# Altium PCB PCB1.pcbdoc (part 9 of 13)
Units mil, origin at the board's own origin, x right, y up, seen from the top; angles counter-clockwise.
Board outline 5895.51 x 5895.51 mil, 8 copper layers (Top Layer, L2_GND1, L3_SIG1, L4_GND2, L5_PWR, L6_SIG2, L7_GND3, Bottom Layer), stack 63.761 mil thick; 673 components, 558 nets, 2797 pads, 1861 vias.
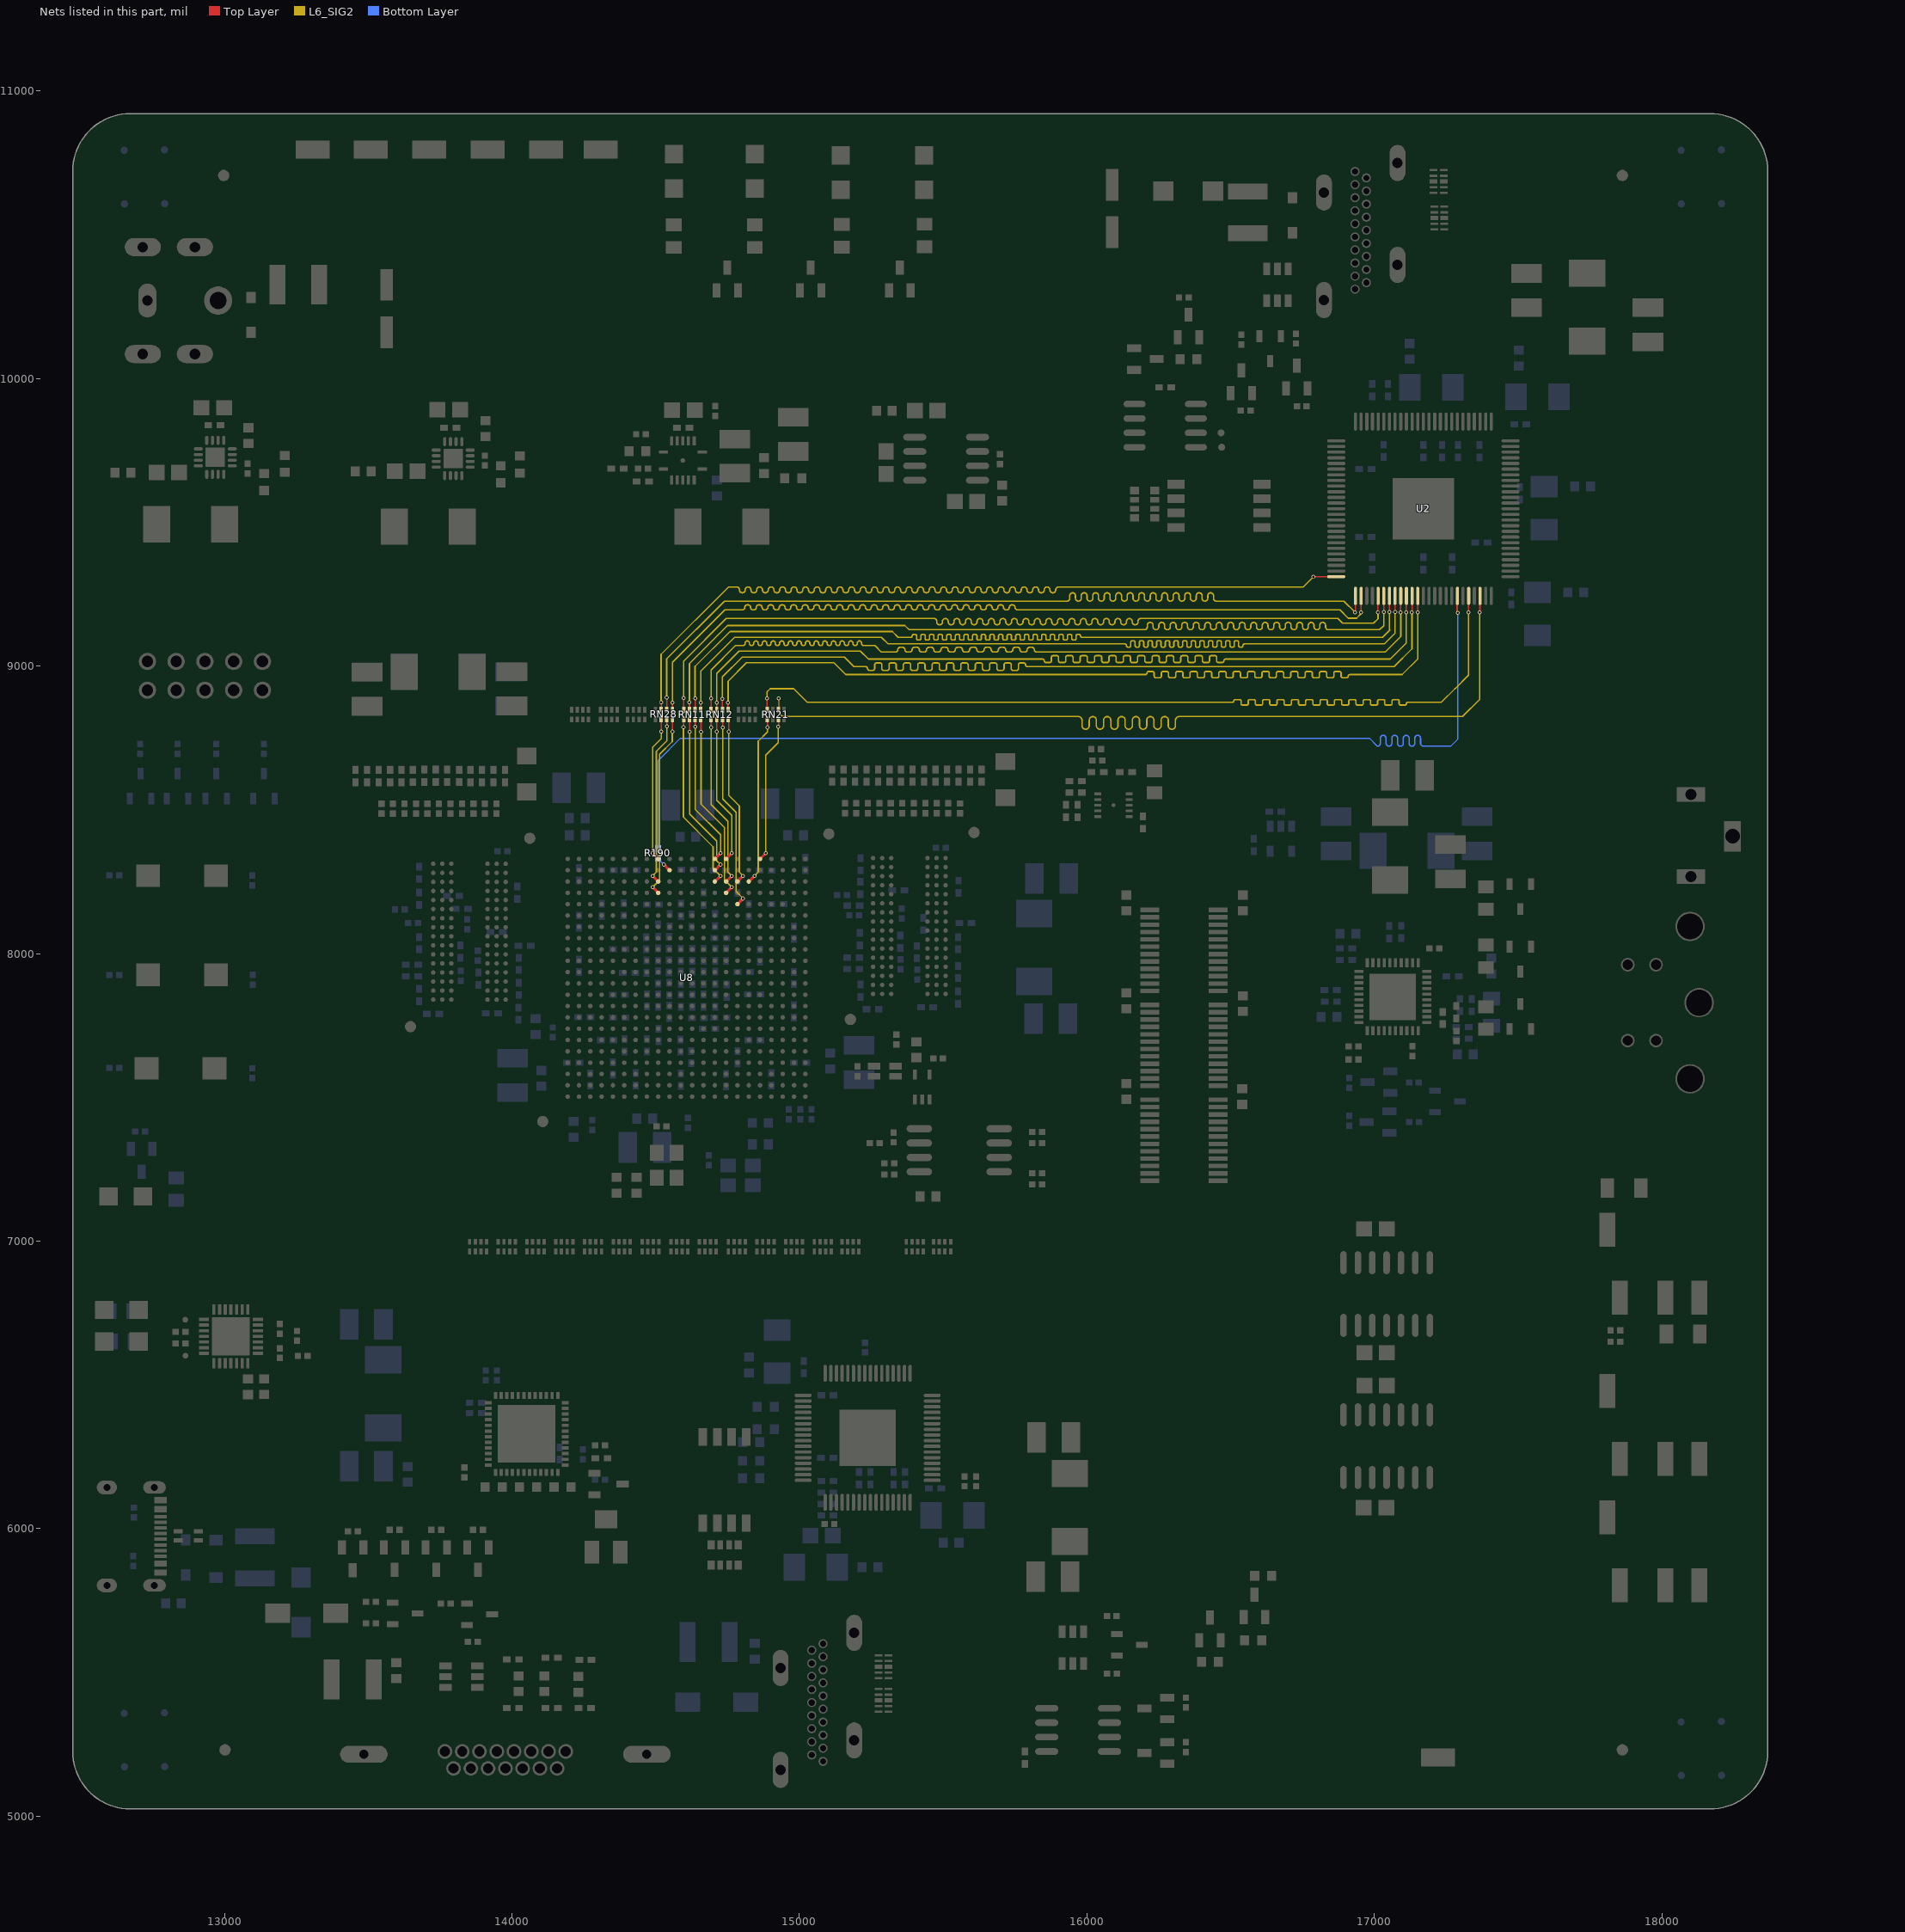
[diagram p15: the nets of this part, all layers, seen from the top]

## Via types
v1: diameter 23.62, hole 15.75, Top Layer to Bottom Layer, 621 vias
v2: diameter 13.8, hole 7.9, Top Layer to Bottom Layer, 567 vias
v3: diameter 13.78, hole 7.87, Top Layer to Bottom Layer, 529 vias
v4: diameter 13.78, hole 7.9, Top Layer to Bottom Layer, 114 vias
v5: diameter 15.75, hole 7.87, Top Layer to Bottom Layer, 16 vias
v6: diameter 24, hole 12, Top Layer to Bottom Layer, 10 vias
v7: diameter 11.81, hole 7.87, Top Layer to Bottom Layer, 4 vias

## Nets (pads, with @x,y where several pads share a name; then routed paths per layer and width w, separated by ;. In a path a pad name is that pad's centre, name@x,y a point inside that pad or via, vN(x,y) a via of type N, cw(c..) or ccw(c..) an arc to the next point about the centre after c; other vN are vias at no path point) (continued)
TFP401_D13: RN28.6 U2.25 | length 3320.2
  Top Layer w4.7: RN28.6@14519.06,8848.52 v3(14519.06,8874) ; v4(16787.36,9310) 16867.87,9310 U2.25@16868.3,9310.42
  L6_SIG2 w5: v3(14519.06,8874) 14519.06,9040.71 14753.36,9275 14781.48,9275 cw(c14781.48,9265) 14791.48,9265 14791.48,9264.5 ccw(c14801.48,9264.5) 14811.48,9264.5 14811.48,9265 cw(c14821.48,9265) 14831.48,9265 14831.48,9264.5 ccw(c14841.48,9264.5) 14851.48,9264.5 14851.48,9265 cw(c14861.48,9265) 14871.48,9265 14871.48,9264.5 ccw(c14881.48,9264.5) 14891.48,9264.5 14891.48,9265 cw(c14901.48,9265) 14911.48,9265 14911.48,9264.5 ccw(c14921.48,9264.5) 14931.48,9264.5 14931.48,9265 cw(c14941.48,9265) 14951.48,9265 14951.48,9264.5 ccw(c14961.48,9264.5) 14971.48,9264.5 14971.48,9265 cw(c14981.48,9265) 14991.48,9265 14991.48,9264.5 ccw(c15001.48,9264.5) 15011.48,9264.5 15011.48,9265 cw(c15021.48,9265) 15031.48,9265 15031.48,9264.5 ccw(c15041.48,9264.5) 15051.48,9264.5 15051.48,9265 cw(c15061.48,9265) 15071.48,9265 15071.48,9264.5 ccw(c15081.48,9264.5) 15091.48,9264.5 15091.48,9265 cw(c15101.48,9265) 15111.48,9265 15111.48,9264.5 ccw(c15121.48,9264.5) 15131.48,9264.5 15131.48,9265 cw(c15141.48,9265) 15151.48,9265 15151.48,9264.5 ccw(c15161.48,9264.5) 15171.48,9264.5 15171.48,9265 cw(c15181.48,9265) 15191.48,9265 15191.48,9264.5 ccw(c15201.48,9264.5) 15211.48,9264.5 15211.48,9265 cw(c15221.48,9265) 15231.48,9265 15231.48,9264.5 ccw(c15241.48,9264.5) 15251.48,9264.5 15251.48,9265 cw(c15261.48,9265) 15271.48,9265 15271.48,9264.5 ccw(c15281.48,9264.5) 15291.48,9264.5 15291.48,9265 cw(c15301.48,9265) 15311.48,9265 15311.48,9264.5 ccw(c15321.48,9264.5) 15331.48,9264.5 15331.48,9265 cw(c15341.48,9265) 15351.48,9265 15351.48,9264.5 ccw(c15361.48,9264.5) 15371.48,9264.5 15371.48,9265 cw(c15381.48,9265) 15391.48,9265 15391.48,9264.5 ccw(c15401.48,9264.5) 15411.48,9264.5 15411.48,9265 cw(c15421.48,9265) 15431.48,9265 15431.48,9264.5 ccw(c15441.48,9264.5) 15451.48,9264.5 15451.48,9265 cw(c15461.48,9265) 15471.48,9265 15471.48,9264.5 ccw(c15481.48,9264.5) 15491.48,9264.5 15491.48,9265 cw(c15501.48,9265) 15511.48,9265 15511.48,9264.5 ccw(c15521.48,9264.5) 15531.48,9264.5 15531.48,9265 cw(c15541.48,9265) 15551.48,9265 15551.48,9264.5 ccw(c15561.48,9264.5) 15571.48,9264.5 15571.48,9265 cw(c15581.48,9265) 15591.48,9265 15591.48,9264.5 ccw(c15601.48,9264.5) 15611.48,9264.5 15611.48,9265 cw(c15621.48,9265) 15631.48,9265 15631.48,9264.5 ccw(c15641.48,9264.5) 15651.48,9264.5 15651.48,9265 cw(c15661.48,9265) 15671.48,9265 15671.48,9264.5 ccw(c15681.48,9264.5) 15691.48,9264.5 15691.48,9265 cw(c15701.48,9265) 15711.48,9265 15711.48,9264.5 ccw(c15721.48,9264.5) 15731.48,9264.5 15731.48,9265 cw(c15741.48,9265) 15751.48,9265 15751.48,9264.5 ccw(c15761.48,9264.5) 15771.48,9264.5 15771.48,9265 cw(c15781.48,9265) 15791.48,9265 15791.48,9264.5 ccw(c15801.48,9264.5) 15811.48,9264.5 15811.48,9265 cw(c15821.48,9265) 15831.48,9265 15831.48,9264.5 ccw(c15841.48,9264.5) 15851.48,9264.5 15851.48,9265 cw(c15861.48,9265) 15871.48,9265 15871.48,9264.5 ccw(c15881.48,9264.5) 15891.48,9264.5 15891.48,9265 cw(c15901.48,9265) 15901.48,9275 16752.36,9275 v4(16787.36,9310)
TFP401_D13_FPGA: RN28.3 U8.A9 | length 506.1
  Top Layer w4.7: RN28.3@14519.06,8814.86 14519.25,8814.67 v3(14519.25,8772.11)
  Top Layer w10: v2(14489.26,8349.07) U8.A9@14508.93,8329.4
  L6_SIG2 w5: v2(14489.26,8349.07) 14489.26,8717.62 14519.25,8747.61 v3(14519.25,8772.11)
TFP401_D14: RN28.7 U2.26 | length 3254.3
  Top Layer w4.7: v3(14538.36,8890) 14538.74,8889.61 RN28.7@14538.74,8848.52 ; v4(16932.36,9187) 16934.51,9189.16 U2.26@16934.51,9239.96
  L6_SIG2 w5: v3(14538.36,8890) 14538.36,9025 14738.97,9225.62 15930.31,9225.62 ccw(c15930.31,9235.62) 15940.31,9235.62 15940.31,9244.61 cw(c15950.31,9244.61) 15960.31,9244.61 15960.31,9235.62 ccw(c15970.31,9235.62) 15980.31,9235.62 15980.31,9244.61 cw(c15990.31,9244.61) 16000.31,9244.61 16000.31,9235.62 ccw(c16010.31,9235.62) 16020.31,9235.62 16020.31,9244.61 cw(c16030.31,9244.61) 16040.31,9244.61 16040.31,9235.62 ccw(c16050.31,9235.62) 16060.31,9235.62 16060.31,9244.61 cw(c16070.31,9244.61) 16080.31,9244.61 16080.31,9235.62 ccw(c16090.31,9235.62) 16100.31,9235.62 16100.31,9244.61 cw(c16110.31,9244.61) 16120.31,9244.61 16120.31,9235.62 ccw(c16130.31,9235.62) 16140.31,9235.62 16140.31,9244.61 cw(c16150.31,9244.61) 16160.31,9244.61 16160.31,9235.62 ccw(c16170.31,9235.62) 16180.31,9235.62 16180.31,9244.61 cw(c16190.31,9244.61) 16200.31,9244.61 16200.31,9235.62 ccw(c16210.31,9235.62) 16220.31,9235.62 16220.31,9244.61 cw(c16230.31,9244.61) 16240.31,9244.61 16240.31,9235.62 ccw(c16250.31,9235.62) 16260.31,9235.62 16260.31,9244.61 cw(c16270.31,9244.61) 16280.31,9244.61 16280.31,9235.62 ccw(c16290.31,9235.62) 16300.31,9235.62 16300.31,9244.61 cw(c16310.31,9244.61) 16320.31,9244.61 16320.31,9235.62 ccw(c16330.31,9235.62) 16340.31,9235.62 16340.31,9244.61 cw(c16350.31,9244.61) 16360.31,9244.61 16360.31,9235.62 ccw(c16370.31,9235.62) 16380.31,9235.62 16380.31,9244.61 cw(c16390.31,9244.61) 16400.31,9244.61 16400.31,9235.62 ccw(c16410.31,9235.62) 16420.31,9235.62 16420.31,9244.61 cw(c16430.31,9244.61) 16440.31,9244.61 16440.31,9235.62 ccw(c16450.31,9235.62) 16450.31,9225.62 16893.74,9225.62 v4(16932.36,9187)
TFP401_D14_FPGA: RN28.2 U8.C9 | length 593
  Top Layer w4.7: v3(14538.72,8790.02) RN28.2@14538.74,8814.86
  Top Layer w10: v2(14489.26,8270.32) U8.C9@14508.93,8250.65
  L6_SIG2 w5: v2(14489.26,8270.32) 14502.23,8283.29 14502.23,8703.72 14538.89,8740.39 14538.89,8789.85 v3(14538.72,8790.02)
TFP401_D15: RN28.8 U2.27 | length 3184.4
  Top Layer w4.7: RN28.8@14558.43,8848.52 v3(14558.43,8873) ; U2.27@16952.55,9241.33 16953.36,9240.52 v4(16953.36,9186)
  L6_SIG2 w5: v3(14558.43,8873) 14558.43,9013.08 14740.74,9195.38 14801.47,9195.38 ccw(c14801.47,9203.97) 14810.06,9203.97 cw(c14818.64,9203.97) 14818.64,9212.56 14821.47,9212.56 cw(c14821.47,9203.97) 14830.06,9203.97 ccw(c14838.64,9203.97) 14838.64,9195.38 14841.47,9195.38 ccw(c14841.47,9203.97) 14850.06,9203.97 cw(c14858.64,9203.97) 14858.64,9212.56 14861.47,9212.56 cw(c14861.47,9203.97) 14870.06,9203.97 ccw(c14878.64,9203.97) 14878.64,9195.38 14881.47,9195.38 ccw(c14881.47,9203.97) 14890.06,9203.97 cw(c14898.64,9203.97) 14898.64,9212.56 14901.47,9212.56 cw(c14901.47,9203.97) 14910.06,9203.97 ccw(c14918.64,9203.97) 14918.64,9195.38 14921.47,9195.38 ccw(c14921.47,9203.97) 14930.06,9203.97 cw(c14938.64,9203.97) 14938.64,9212.56 14941.47,9212.56 cw(c14941.47,9203.97) 14950.06,9203.97 ccw(c14958.64,9203.97) 14958.64,9195.38 14961.47,9195.38 ccw(c14961.47,9203.97) 14970.06,9203.97 cw(c14978.64,9203.97) 14978.64,9212.56 14981.47,9212.56 cw(c14981.47,9203.97) 14990.06,9203.97 ccw(c14998.64,9203.97) 14998.64,9195.38 15001.47,9195.38 ccw(c15001.47,9203.97) 15010.06,9203.97 cw(c15018.64,9203.97) 15018.64,9212.56 15021.47,9212.56 cw(c15021.47,9203.97) 15030.06,9203.97 ccw(c15038.64,9203.97) 15038.64,9195.38 15041.47,9195.38 ccw(c15041.47,9203.97) 15050.06,9203.97 cw(c15058.64,9203.97) 15058.64,9212.56 15061.47,9212.56 cw(c15061.47,9203.97) 15070.06,9203.97 ccw(c15078.64,9203.97) 15078.64,9195.38 15081.47,9195.38 ccw(c15081.47,9203.97) 15090.06,9203.97 cw(c15098.64,9203.97) 15098.64,9212.56 15101.47,9212.56 cw(c15101.47,9203.97) 15110.06,9203.97 ccw(c15118.64,9203.97) 15118.64,9195.38 15121.47,9195.38 ccw(c15121.47,9203.97) 15130.06,9203.97 cw(c15138.64,9203.97) 15138.64,9212.56 15141.47,9212.56 cw(c15141.47,9203.97) 15150.06,9203.97 ccw(c15158.64,9203.97) 15158.64,9195.38 15161.47,9195.38 ccw(c15161.47,9203.97) 15170.06,9203.97 cw(c15178.64,9203.97) 15178.64,9212.56 15181.47,9212.56 cw(c15181.47,9203.97) 15190.06,9203.97 ccw(c15198.64,9203.97) 15198.64,9195.38 15201.47,9195.38 ccw(c15201.47,9203.97) 15210.06,9203.97 cw(c15218.64,9203.97) 15218.64,9212.56 15221.47,9212.56 cw(c15221.47,9203.97) 15230.06,9203.97 ccw(c15238.64,9203.97) 15238.64,9195.38 15241.47,9195.38 ccw(c15241.47,9203.97) 15250.06,9203.97 cw(c15258.64,9203.97) 15258.64,9212.56 15261.47,9212.56 cw(c15261.47,9203.97) 15270.06,9203.97 ccw(c15278.64,9203.97) 15278.64,9195.38 15281.47,9195.38 ccw(c15281.47,9203.97) 15290.06,9203.97 cw(c15298.64,9203.97) 15298.64,9212.56 15301.47,9212.56 cw(c15301.47,9203.97) 15310.06,9203.97 ccw(c15318.64,9203.97) 15318.64,9195.38 15321.47,9195.38 ccw(c15321.47,9203.97) 15330.06,9203.97 cw(c15338.64,9203.97) 15338.64,9212.56 15341.47,9212.56 cw(c15341.47,9203.97) 15350.06,9203.97 ccw(c15358.64,9203.97) 15358.64,9195.38 15361.47,9195.38 ccw(c15361.47,9203.97) 15370.06,9203.97 cw(c15378.64,9203.97) 15378.64,9212.56 15381.47,9212.56 cw(c15381.47,9203.97) 15390.06,9203.97 ccw(c15398.64,9203.97) 15398.64,9195.38 15401.47,9195.38 ccw(c15401.47,9203.97) 15410.06,9203.97 cw(c15418.64,9203.97) 15418.64,9212.56 15421.47,9212.56 cw(c15421.47,9203.97) 15430.06,9203.97 ccw(c15438.64,9203.97) 15438.64,9195.38 15441.47,9195.38 ccw(c15441.47,9203.97) 15450.06,9203.97 cw(c15458.64,9203.97) 15458.64,9212.56 15461.47,9212.56 cw(c15461.47,9203.97) 15470.06,9203.97 ccw(c15478.64,9203.97) 15478.64,9195.38 15481.47,9195.38 ccw(c15481.47,9203.97) 15490.06,9203.97 cw(c15498.64,9203.97) 15498.64,9212.56 15501.47,9212.56 cw(c15501.47,9203.97) 15510.06,9203.97 ccw(c15518.64,9203.97) 15518.64,9195.38 15521.47,9195.38 ccw(c15521.47,9203.97) 15530.06,9203.97 cw(c15538.64,9203.97) 15538.64,9212.56 15541.47,9212.56 cw(c15541.47,9203.97) 15550.06,9203.97 ccw(c15558.64,9203.97) 15558.64,9195.38 15561.47,9195.38 ccw(c15561.47,9203.97) 15570.06,9203.97 cw(c15578.64,9203.97) 15578.64,9212.56 15581.47,9212.56 cw(c15581.47,9203.97) 15590.06,9203.97 ccw(c15598.64,9203.97) 15598.64,9195.38 15601.47,9195.38 ccw(c15601.47,9203.97) 15610.06,9203.97 cw(c15618.64,9203.97) 15618.64,9212.56 15621.47,9212.56 cw(c15621.47,9203.97) 15630.06,9203.97 ccw(c15638.64,9203.97) 15638.64,9195.38 15641.47,9195.38 ccw(c15641.47,9203.97) 15650.06,9203.97 cw(c15658.64,9203.97) 15658.64,9212.56 15661.47,9212.56 cw(c15661.47,9203.97) 15670.06,9203.97 ccw(c15678.64,9203.97) 15678.64,9195.38 15681.47,9195.38 ccw(c15681.47,9203.97) 15690.06,9203.97 cw(c15698.64,9203.97) 15698.64,9212.56 15701.47,9212.56 cw(c15701.47,9203.97) 15710.06,9203.97 ccw(c15718.64,9203.97) 15718.64,9195.38 15721.47,9195.38 ccw(c15721.47,9203.97) 15730.06,9203.97 cw(c15738.64,9203.97) 15738.64,9212.56 15741.47,9212.56 cw(c15741.47,9203.97) 15750.06,9203.97 ccw(c15758.64,9203.97) 15758.64,9195.38 16880.05,9195.38 16909.04,9166.39 ; 16909.17,9166.26 16909.04,9166.39 ; 16938.3,9166.39 16937.69,9166.39 ; v4(16953.36,9186) 16953.36,9182.06 16937.69,9166.39 ; 16909.04,9166.39 16937.69,9166.39
TFP401_D15_FPGA: RN28.1 U8.D9 | length 640.4
  Top Layer w4.7: v3(14558.02,8771.64) 14558.43,8772.05 RN28.1@14558.43,8814.86
  Top Layer w10: v2(14489.26,8230.95) U8.D9@14508.93,8211.27
  L6_SIG2 w5: v2(14489.26,8230.95) 14513.82,8255.52 14513.82,8692.94 14557.9,8737.02 14557.9,8771.52 v3(14558.02,8771.64)
TFP401_D16: RN11.5 U2.30 | length 3210.6
  Top Layer w4.7: v3(14597.36,8889) 14597.83,8888.53 RN11.5@14597.83,8847.83 ; v4(17012.36,9187) U2.30@17012.36,9237.18
  L6_SIG2 w5: v3(14597.36,8889) 14597.36,9017 14745.58,9165.22 15467.67,9165.22 cw(c15467.67,9155.22) 15477.67,9155.22 15477.67,9153.33 ccw(c15487.67,9153.33) 15497.67,9153.33 15497.67,9155.22 cw(c15507.67,9155.22) 15517.67,9155.22 15517.67,9153.33 ccw(c15527.67,9153.33) 15537.67,9153.33 15537.67,9155.22 cw(c15547.67,9155.22) 15557.67,9155.22 15557.67,9153.33 ccw(c15567.67,9153.33) 15577.67,9153.33 15577.67,9155.22 cw(c15587.67,9155.22) 15597.67,9155.22 15597.67,9153.33 ccw(c15607.67,9153.33) 15617.67,9153.33 15617.67,9155.22 cw(c15627.67,9155.22) 15637.67,9155.22 15637.67,9153.33 ccw(c15647.67,9153.33) 15657.67,9153.33 15657.67,9155.22 cw(c15667.67,9155.22) 15677.67,9155.22 15677.67,9153.33 ccw(c15687.67,9153.33) 15697.67,9153.33 15697.67,9155.22 cw(c15707.67,9155.22) 15717.67,9155.22 15717.67,9153.33 ccw(c15727.67,9153.33) 15737.67,9153.33 15737.67,9155.22 cw(c15747.67,9155.22) 15757.67,9155.22 15757.67,9153.33 ccw(c15767.67,9153.33) 15777.67,9153.33 15777.67,9155.22 cw(c15787.67,9155.22) 15797.67,9155.22 15797.67,9153.33 ccw(c15807.67,9153.33) 15817.67,9153.33 15817.67,9155.22 cw(c15827.67,9155.22) 15837.67,9155.22 15837.67,9153.33 ccw(c15847.67,9153.33) 15857.67,9153.33 15857.67,9155.22 cw(c15867.67,9155.22) 15877.67,9155.22 15877.67,9153.33 ccw(c15887.67,9153.33) 15897.67,9153.33 15897.67,9155.22 cw(c15907.67,9155.22) 15917.67,9155.22 15917.67,9153.33 ccw(c15927.67,9153.33) 15937.67,9153.33 15937.67,9155.22 cw(c15947.67,9155.22) 15957.67,9155.22 15957.67,9153.33 ccw(c15967.67,9153.33) 15977.67,9153.33 15977.67,9155.22 cw(c15987.67,9155.22) 15997.67,9155.22 15997.67,9153.33 ccw(c16007.67,9153.33) 16017.67,9153.33 16017.67,9155.22 cw(c16027.67,9155.22) 16037.67,9155.22 16037.67,9153.33 ccw(c16047.67,9153.33) 16057.67,9153.33 16057.67,9155.22 cw(c16067.67,9155.22) 16077.67,9155.22 16077.67,9153.33 ccw(c16087.67,9153.33) 16097.67,9153.33 16097.67,9155.22 cw(c16107.67,9155.22) 16117.67,9155.22 16117.67,9153.33 ccw(c16127.67,9153.33) 16137.67,9153.33 16137.67,9155.22 cw(c16147.67,9155.22) 16157.67,9155.22 16157.67,9153.33 ccw(c16167.67,9153.33) 16177.67,9153.33 16177.67,9155.22 cw(c16187.67,9155.22) 16187.67,9165.22 16873.04,9165.22 16889.04,9149.21 16996.78,9149.21 16996.86,9149.13 16997.09,9149.13 17012.36,9164.39 v4(17012.36,9187)
TFP401_D16_FPGA: RN11.4 U8.C14 | length 625.5
  Top Layer w4.7: v3(14596.62,8787.81) 14597.83,8789.02 RN11.4@14597.83,8814.17
  Top Layer w10: U8.C14@14705.78,8250.65 v2(14725.46,8270.32)
  L6_SIG2 w5: v3(14596.62,8787.81) 14596.62,8474.41 14699.84,8371.19 14699.84,8295.94 v2(14725.46,8270.32)
TFP401_D17: RN11.6 U2.31 | length 3279.6
  Top Layer w4.7: v3(14617.36,8874) 14617.52,8873.84 RN11.6@14617.52,8847.83 ; U2.31@17031.51,9237.54 17032.36,9236.7 v4(17032.36,9188)
  L6_SIG2 w5: v3(14617.36,8874) 14617.36,9009 14749.43,9141.07 15366.72,9141.07 15381.56,9126.23 16199.99,9126.23 ccw(c16199.99,9136.23) 16209.99,9136.23 16209.99,9141.66 cw(c16219.99,9141.66) 16229.99,9141.66 16229.99,9136.23 ccw(c16239.99,9136.23) 16249.99,9136.23 16249.99,9141.66 cw(c16259.99,9141.66) 16269.99,9141.66 16269.99,9136.23 ccw(c16279.99,9136.23) 16289.99,9136.23 16289.99,9141.66 cw(c16299.99,9141.66) 16309.99,9141.66 16309.99,9136.23 ccw(c16319.99,9136.23) 16329.99,9136.23 16329.99,9141.66 cw(c16339.99,9141.66) 16349.99,9141.66 16349.99,9136.23 ccw(c16359.99,9136.23) 16369.99,9136.23 16369.99,9141.66 cw(c16379.99,9141.66) 16389.99,9141.66 16389.99,9136.23 ccw(c16399.99,9136.23) 16409.99,9136.23 16409.99,9141.66 cw(c16419.99,9141.66) 16429.99,9141.66 16429.99,9136.23 ccw(c16439.99,9136.23) 16449.99,9136.23 16449.99,9141.66 cw(c16459.99,9141.66) 16469.99,9141.66 16469.99,9136.23 ccw(c16479.99,9136.23) 16489.99,9136.23 16489.99,9141.66 cw(c16499.99,9141.66) 16509.99,9141.66 16509.99,9136.23 ccw(c16519.99,9136.23) 16529.99,9136.23 16529.99,9141.66 cw(c16539.99,9141.66) 16549.99,9141.66 16549.99,9136.23 ccw(c16559.99,9136.23) 16569.99,9136.23 16569.99,9141.66 cw(c16579.99,9141.66) 16589.99,9141.66 16589.99,9136.23 ccw(c16599.99,9136.23) 16609.99,9136.23 16609.99,9141.66 cw(c16619.99,9141.66) 16629.99,9141.66 16629.99,9136.23 ccw(c16639.99,9136.23) 16649.99,9136.23 16649.99,9141.66 cw(c16659.99,9141.66) 16669.99,9141.66 16669.99,9136.23 ccw(c16679.99,9136.23) 16689.99,9136.23 16689.99,9141.66 cw(c16699.99,9141.66) 16709.99,9141.66 16709.99,9136.23 ccw(c16719.99,9136.23) 16729.99,9136.23 16729.99,9141.66 cw(c16739.99,9141.66) 16749.99,9141.66 16749.99,9136.23 ccw(c16759.99,9136.23) 16769.99,9136.23 16769.99,9141.66 cw(c16779.99,9141.66) 16789.99,9141.66 16789.99,9136.23 ccw(c16799.99,9136.23) 16809.99,9136.23 16809.99,9141.66 cw(c16819.99,9141.66) 16829.99,9141.66 16829.99,9136.23 ccw(c16839.99,9136.23) 16839.99,9126.23 17018.25,9126.23 17032.33,9140.32 v4(17032.36,9188)
TFP401_D17_FPGA: RN11.3 U8.B14 | length 577
  Top Layer w4.7: RN11.3@14617.52,8814.17 14618.37,8813.32 v3(14618.37,8770.75)
  Top Layer w10: U8.B14@14705.78,8290.01 v2(14725.46,8309.69)
  L6_SIG2 w5: v3@14618.31,8770.69 14618.31,8485.16 14712.29,8391.18 14712.29,8322.86 v2(14725.46,8309.69)
TFP401_D18: RN11.7 U2.32 | length 3341.1
  Top Layer w4.7: RN11.7@14637.2,8847.83 v3(14637.2,8888) ; U2.32@17050.76,9236.48 17052.36,9234.88 v4(17052.36,9188)
  L6_SIG2 w5: v3(14637.2,8888) 14637.2,8998.84 14758.55,9120.19 15323.32,9120.19 15343.47,9100.05 15387.61,9100.05 ccw(c15387.61,9104.92) 15392.48,9104.92 cw(c15397.35,9104.92) 15397.35,9109.79 15402.61,9109.79 cw(c15402.61,9104.92) 15407.48,9104.92 15407.48,9095.18 ccw(c15412.35,9095.18) 15412.35,9090.31 15417.61,9090.31 ccw(c15417.61,9095.18) 15422.48,9095.18 15422.48,9104.92 cw(c15427.35,9104.92) 15427.35,9109.79 15432.61,9109.79 cw(c15432.61,9104.92) 15437.48,9104.92 15437.48,9095.18 ccw(c15442.35,9095.18) 15442.35,9090.31 15447.61,9090.31 ccw(c15447.61,9095.18) 15452.48,9095.18 15452.48,9104.92 cw(c15457.35,9104.92) 15457.35,9109.79 15462.61,9109.79 cw(c15462.61,9104.92) 15467.48,9104.92 15467.48,9095.18 ccw(c15472.35,9095.18) 15472.35,9090.31 15477.61,9090.31 ccw(c15477.61,9095.18) 15482.48,9095.18 15482.48,9104.92 cw(c15487.35,9104.92) 15487.35,9109.79 15492.61,9109.79 cw(c15492.61,9104.92) 15497.48,9104.92 15497.48,9095.18 ccw(c15502.35,9095.18) 15502.35,9090.31 15507.61,9090.31 ccw(c15507.61,9095.18) 15512.48,9095.18 15512.48,9104.92 cw(c15517.35,9104.92) 15517.35,9109.79 15522.61,9109.79 cw(c15522.61,9104.92) 15527.48,9104.92 15527.48,9095.18 ccw(c15532.35,9095.18) 15532.35,9090.31 15537.61,9090.31 ccw(c15537.61,9095.18) 15542.48,9095.18 15542.48,9104.92 cw(c15547.35,9104.92) 15547.35,9109.79 15552.61,9109.79 cw(c15552.61,9104.92) 15557.48,9104.92 15557.48,9095.18 ccw(c15562.35,9095.18) 15562.35,9090.31 15567.61,9090.31 ccw(c15567.61,9095.18) 15572.48,9095.18 15572.48,9104.92 cw(c15577.35,9104.92) 15577.35,9109.79 15582.61,9109.79 cw(c15582.61,9104.92) 15587.48,9104.92 15587.48,9095.18 ccw(c15592.35,9095.18) 15592.35,9090.31 15597.61,9090.31 ccw(c15597.61,9095.18) 15602.48,9095.18 15602.48,9104.92 cw(c15607.35,9104.92) 15607.35,9109.79 15612.61,9109.79 cw(c15612.61,9104.92) 15617.48,9104.92 15617.48,9095.18 ccw(c15622.35,9095.18) 15622.35,9090.31 15627.61,9090.31 ccw(c15627.61,9095.18) 15632.48,9095.18 15632.48,9104.92 cw(c15637.35,9104.92) 15637.35,9109.79 15642.61,9109.79 cw(c15642.61,9104.92) 15647.48,9104.92 15647.48,9095.18 ccw(c15652.35,9095.18) 15652.35,9090.31 15657.61,9090.31 ccw(c15657.61,9095.18) 15662.48,9095.18 15662.48,9104.92 cw(c15667.35,9104.92) 15667.35,9109.79 15672.61,9109.79 cw(c15672.61,9104.92) 15677.48,9104.92 15677.48,9095.18 ccw(c15682.35,9095.18) 15682.35,9090.31 15687.61,9090.31 ccw(c15687.61,9095.18) 15692.48,9095.18 15692.48,9104.92 cw(c15697.35,9104.92) 15697.35,9109.79 15702.61,9109.79 cw(c15702.61,9104.92) 15707.48,9104.92 15707.48,9095.18 ccw(c15712.35,9095.18) 15712.35,9090.31 15717.61,9090.31 ccw(c15717.61,9095.18) 15722.48,9095.18 15722.48,9104.92 cw(c15727.35,9104.92) 15727.35,9109.79 15732.61,9109.79 cw(c15732.61,9104.92) 15737.48,9104.92 15737.48,9095.18 ccw(c15742.35,9095.18) 15742.35,9090.31 15747.61,9090.31 ccw(c15747.61,9095.18) 15752.48,9095.18 15752.48,9104.92 cw(c15757.35,9104.92) 15757.35,9109.79 15762.61,9109.79 cw(c15762.61,9104.92) 15767.48,9104.92 15767.48,9095.18 ccw(c15772.35,9095.18) 15772.35,9090.31 15777.61,9090.31 ccw(c15777.61,9095.18) 15782.48,9095.18 15782.48,9104.92 cw(c15787.35,9104.92) 15787.35,9109.79 15792.61,9109.79 cw(c15792.61,9104.92) 15797.48,9104.92 15797.48,9095.18 ccw(c15802.35,9095.18) 15802.35,9090.31 15807.61,9090.31 ccw(c15807.61,9095.18) 15812.48,9095.18 15812.48,9104.92 cw(c15817.35,9104.92) 15817.35,9109.79 15822.61,9109.79 cw(c15822.61,9104.92) 15827.48,9104.92 15827.48,9095.18 ccw(c15832.35,9095.18) 15832.35,9090.31 15837.61,9090.31 ccw(c15837.61,9095.18) 15842.48,9095.18 15842.48,9104.92 cw(c15847.35,9104.92) 15847.35,9109.79 15852.61,9109.79 cw(c15852.61,9104.92) 15857.48,9104.92 15857.48,9095.18 ccw(c15862.35,9095.18) 15862.35,9090.31 15867.61,9090.31 ccw(c15867.61,9095.18) 15872.48,9095.18 15872.48,9104.92 cw(c15877.35,9104.92) 15877.35,9109.79 15882.61,9109.79 cw(c15882.61,9104.92) 15887.48,9104.92 15887.48,9095.18 ccw(c15892.35,9095.18) 15892.35,9090.31 15897.61,9090.31 ccw(c15897.61,9095.18) 15902.48,9095.18 15902.48,9104.92 cw(c15907.35,9104.92) 15907.35,9109.79 15912.61,9109.79 cw(c15912.61,9104.92) 15917.48,9104.92 15917.48,9095.18 ccw(c15922.35,9095.18) 15922.35,9090.31 15927.61,9090.31 ccw(c15927.61,9095.18) 15932.48,9095.18 15932.48,9104.92 cw(c15937.35,9104.92) 15937.35,9109.79 15942.61,9109.79 cw(c15942.61,9104.92) 15947.48,9104.92 15947.48,9095.18 ccw(c15952.35,9095.18) 15952.35,9090.31 15957.61,9090.31 ccw(c15957.61,9095.18) 15962.48,9095.18 15962.48,9104.92 cw(c15967.35,9104.92) 15967.35,9109.79 15972.61,9109.79 cw(c15972.61,9104.92) 15977.48,9104.92 ccw(c15982.35,9104.92) 15982.35,9100.05 17028.41,9100.05 17053.45,9125.09 17052.36,9126.18 v4(17052.36,9188)
TFP401_D18_FPGA: RN11.2 U8.A14 | length 529.5
  Top Layer w4.7: RN11.2@14637.2,8814.17 14637.2,8789.08 v3(14637.63,8788.65)
  Top Layer w10: U8.A14@14705.78,8329.4 v2(14725.46,8349.07)
  L6_SIG2 w5: v3(14637.63,8788.65) 14637.77,8788.51 14637.77,8500.85 14725.46,8413.17 v2(14725.46,8349.07)
TFP401_D19: RN11.8 U2.33 | length 3224.2
  Top Layer w4.7: RN11.8@14656.89,8847.83 v3(14656.89,8873) ; U2.33@17071.53,9236.02 17071.53,9188.83 v4(17072.36,9188)
  L6_SIG2 w5: v3(14656.89,8873) 14656.89,8982.53 14774.57,9100.21 15285.17,9100.21 15308.48,9076.9 16131.89,9076.9 cw(c16131.89,9071.21) 16137.59,9071.21 ccw(c16143.28,9071.21) 16143.28,9065.51 16146.89,9065.51 ccw(c16146.89,9071.21) 16152.59,9071.21 16152.59,9082.6 cw(c16158.28,9082.6) 16158.28,9088.29 16161.89,9088.29 cw(c16161.89,9082.6) 16167.59,9082.6 16167.59,9071.21 ccw(c16173.28,9071.21) 16173.28,9065.51 16176.89,9065.51 ccw(c16176.89,9071.21) 16182.59,9071.21 16182.59,9082.6 cw(c16188.28,9082.6) 16188.28,9088.29 16191.89,9088.29 cw(c16191.89,9082.6) 16197.59,9082.6 16197.59,9071.21 ccw(c16203.28,9071.21) 16203.28,9065.51 16206.89,9065.51 ccw(c16206.89,9071.21) 16212.59,9071.21 16212.59,9082.6 cw(c16218.28,9082.6) 16218.28,9088.29 16221.89,9088.29 cw(c16221.89,9082.6) 16227.59,9082.6 16227.59,9071.21 ccw(c16233.28,9071.21) 16233.28,9065.51 16236.89,9065.51 ccw(c16236.89,9071.21) 16242.59,9071.21 16242.59,9082.6 cw(c16248.28,9082.6) 16248.28,9088.29 16251.89,9088.29 cw(c16251.89,9082.6) 16257.59,9082.6 16257.59,9071.21 ccw(c16263.28,9071.21) 16263.28,9065.51 16266.89,9065.51 ccw(c16266.89,9071.21) 16272.59,9071.21 16272.59,9082.6 cw(c16278.28,9082.6) 16278.28,9088.29 16281.89,9088.29 cw(c16281.89,9082.6) 16287.59,9082.6 16287.59,9071.21 ccw(c16293.28,9071.21) 16293.28,9065.51 16296.89,9065.51 ccw(c16296.89,9071.21) 16302.59,9071.21 16302.59,9082.6 cw(c16308.28,9082.6) 16308.28,9088.29 16311.89,9088.29 cw(c16311.89,9082.6) 16317.59,9082.6 16317.59,9071.21 ccw(c16323.28,9071.21) 16323.28,9065.51 16326.89,9065.51 ccw(c16326.89,9071.21) 16332.59,9071.21 16332.59,9082.6 cw(c16338.28,9082.6) 16338.28,9088.29 16341.89,9088.29 cw(c16341.89,9082.6) 16347.59,9082.6 16347.59,9071.21 ccw(c16353.28,9071.21) 16353.28,9065.51 16356.89,9065.51 ccw(c16356.89,9071.21) 16362.59,9071.21 16362.59,9082.6 cw(c16368.28,9082.6) 16368.28,9088.29 16371.89,9088.29 cw(c16371.89,9082.6) 16377.59,9082.6 16377.59,9071.21 ccw(c16383.28,9071.21) 16383.28,9065.51 16386.89,9065.51 ccw(c16386.89,9071.21) 16392.59,9071.21 16392.59,9082.6 cw(c16398.28,9082.6) 16398.28,9088.29 16401.89,9088.29 cw(c16401.89,9082.6) 16407.59,9082.6 16407.59,9071.21 ccw(c16413.28,9071.21) 16413.28,9065.51 16416.89,9065.51 ccw(c16416.89,9071.21) 16422.59,9071.21 16422.59,9082.6 cw(c16428.28,9082.6) 16428.28,9088.29 16431.89,9088.29 cw(c16431.89,9082.6) 16437.59,9082.6 16437.59,9071.21 ccw(c16443.28,9071.21) 16443.28,9065.51 16446.89,9065.51 ccw(c16446.89,9071.21) 16452.59,9071.21 16452.59,9082.6 cw(c16458.28,9082.6) 16458.28,9088.29 16461.89,9088.29 cw(c16461.89,9082.6) 16467.59,9082.6 16467.59,9071.21 ccw(c16473.28,9071.21) 16473.28,9065.51 16476.89,9065.51 ccw(c16476.89,9071.21) 16482.59,9071.21 16482.59,9082.6 cw(c16488.28,9082.6) 16488.28,9088.29 16491.89,9088.29 cw(c16491.89,9082.6) 16497.59,9082.6 16497.59,9071.21 ccw(c16503.28,9071.21) 16503.28,9065.51 16506.89,9065.51 ccw(c16506.89,9071.21) 16512.59,9071.21 16512.59,9082.6 cw(c16518.28,9082.6) 16518.28,9088.29 16521.89,9088.29 cw(c16521.89,9082.6) 16527.59,9082.6 16527.59,9071.21 ccw(c16533.28,9071.21) 16533.28,9065.51 16536.89,9065.51 ccw(c16536.89,9071.21) 16542.59,9071.21 cw(c16548.28,9071.21) 16548.28,9076.9 17034.84,9076.9 17071.96,9114.02 17071.96,9187.6 v4(17072.36,9188)
TFP401_D19_FPGA: RN11.1 U8.D15 | length 655.8
  Top Layer w4.7: RN11.1@14656.89,8814.17 14657.89,8813.17 v3(14657.89,8771.29)
  Top Layer w10: U8.D15@14745.16,8211.27 v2(14764.84,8230.95)
  L6_SIG2 w5: v3(14657.89,8771.29) 14657.89,8519.61 14739.41,8438.09 14739.41,8256.38 v2(14764.84,8230.95)
TFP401_D20: RN12.5 U2.34 | length 3189.9
  Top Layer w4.7: RN12.5@14692.83,8847.83 v3(14692.83,8887) ; v4(17091.36,9187) 17091.36,9232.51 U2.34@17091.53,9232.69
  L6_SIG2 w5: v3(14692.83,8887) 14692.83,8986.47 14777.43,9071.07 14803.77,9071.07 ccw(c14803.77,9078.57) 14811.27,9078.57 14811.27,9079.75 cw(c14818.77,9079.75) 14826.27,9079.75 14826.27,9078.57 ccw(c14833.77,9078.57) 14841.27,9078.57 14841.27,9079.75 cw(c14848.77,9079.75) 14856.27,9079.75 14856.27,9078.57 ccw(c14863.77,9078.57) 14871.27,9078.57 14871.27,9079.75 cw(c14878.77,9079.75) 14886.27,9079.76 14886.27,9078.57 ccw(c14893.77,9078.57) 14901.27,9078.57 14901.27,9079.76 cw(c14908.77,9079.76) 14916.27,9079.76 14916.27,9078.57 ccw(c14923.77,9078.58) 14931.27,9078.58 14931.27,9079.76 cw(c14938.77,9079.76) 14946.27,9079.76 14946.27,9078.58 ccw(c14953.77,9078.58) 14961.27,9078.58 14961.27,9079.76 cw(c14968.77,9079.76) 14976.27,9079.76 14976.27,9078.58 ccw(c14983.77,9078.58) 14991.27,9078.58 14991.27,9079.76 cw(c14998.77,9079.76) 15006.27,9079.76 15006.27,9078.58 ccw(c15013.77,9078.58) 15021.27,9078.58 15021.27,9079.76 cw(c15028.77,9079.76) 15036.27,9079.76 15036.27,9078.58 ccw(c15043.77,9078.58) 15051.27,9078.58 15051.27,9079.76 cw(c15058.77,9079.76) 15066.27,9079.76 15066.27,9078.58 ccw(c15073.77,9078.58) 15081.27,9078.58 15081.27,9079.76 cw(c15088.77,9079.76) 15096.27,9079.76 15096.27,9078.58 ccw(c15103.77,9078.58) 15111.27,9078.58 15111.27,9079.76 cw(c15118.77,9079.76) 15126.27,9079.76 15126.27,9078.58 ccw(c15133.77,9078.58) 15141.27,9078.58 15141.27,9079.76 cw(c15148.77,9079.76) 15156.27,9079.76 15156.27,9078.58 ccw(c15163.77,9078.58) 15171.27,9078.58 15171.27,9079.76 cw(c15178.77,9079.76) 15186.27,9079.76 15186.27,9078.58 ccw(c15193.77,9078.58) 15201.27,9078.58 15201.27,9079.76 cw(c15208.77,9079.76) 15216.27,9079.76 15216.27,9078.58 ccw(c15223.77,9078.58) 15223.77,9071.08 15262.29,9071.08 15284.46,9048.91 15334.11,9048.91 ccw(c15334.11,9056.92) 15342.12,9056.92 cw(c15350.14,9056.92) 15350.14,9064.93 15359.11,9064.93 cw(c15359.11,9056.92) 15367.12,9056.92 ccw(c15375.14,9056.92) 15375.14,9048.91 15384.11,9048.91 ccw(c15384.11,9056.92) 15392.12,9056.92 cw(c15400.14,9056.92) 15400.14,9064.93 15409.11,9064.93 cw(c15409.11,9056.92) 15417.12,9056.92 ccw(c15425.14,9056.92) 15425.14,9048.91 15434.11,9048.91 ccw(c15434.11,9056.92) 15442.12,9056.92 cw(c15450.14,9056.92) 15450.14,9064.93 15459.11,9064.93 cw(c15459.11,9056.92) 15467.12,9056.92 ccw(c15475.14,9056.92) 15475.14,9048.91 15484.11,9048.91 ccw(c15484.11,9056.92) 15492.12,9056.92 cw(c15500.14,9056.92) 15500.14,9064.93 15509.11,9064.93 cw(c15509.11,9056.92) 15517.12,9056.92 ccw(c15525.14,9056.92) 15525.14,9048.91 15534.11,9048.91 ccw(c15534.11,9056.92) 15542.12,9056.92 cw(c15550.14,9056.92) 15550.14,9064.93 15559.11,9064.93 cw(c15559.11,9056.92) 15567.12,9056.92 ccw(c15575.14,9056.92) 15575.14,9048.91 15584.11,9048.91 ccw(c15584.11,9056.92) 15592.12,9056.92 cw(c15600.14,9056.92) 15600.14,9064.93 15609.11,9064.93 cw(c15609.11,9056.92) 15617.12,9056.92 ccw(c15625.14,9056.92) 15625.14,9048.91 15634.11,9048.91 ccw(c15634.11,9056.92) 15642.12,9056.92 cw(c15650.14,9056.92) 15650.14,9064.93 15659.11,9064.93 cw(c15659.11,9056.92) 15667.12,9056.92 ccw(c15675.14,9056.92) 15675.14,9048.91 15684.11,9048.91 ccw(c15684.11,9056.92) 15692.12,9056.92 cw(c15700.14,9056.92) 15700.14,9064.93 15709.11,9064.93 cw(c15709.11,9056.92) 15717.12,9056.92 ccw(c15725.14,9056.92) 15725.14,9048.91 15734.11,9048.91 ccw(c15734.11,9056.92) 15742.12,9056.92 cw(c15750.14,9056.92) 15750.14,9064.93 15759.11,9064.93 cw(c15759.11,9056.92) 15767.12,9056.92 ccw(c15775.14,9056.92) 15775.14,9048.91 15784.11,9048.91 ccw(c15784.11,9056.92) 15792.12,9056.92 cw(c15800.14,9056.92) 15800.14,9064.93 15809.11,9064.93 cw(c15809.11,9056.92) 15817.12,9056.92 ccw(c15825.14,9056.92) 15825.14,9048.91 17037.9,9048.91 17091.7,9102.71 17091.7,9186.66 v4(17091.36,9187)
TFP401_D20_FPGA: RN12.4 U8.C15 | length 601.8
  Top Layer w4.7: RN12.4@14692.83,8814.17 14693.27,8813.73 v3(14693.27,8786.68)
  Top Layer w10: U8.C15@14745.16,8250.65 v2(14764.84,8270.32)
  L6_SIG2 w5: v3(14693.27,8786.68) 14692.92,8786.34 14692.92,8518.45 14751.84,8459.54 14751.84,8283.32 v2(14764.84,8270.32)
TFP401_D21: RN12.6 U2.35 | length 3211.4
  Top Layer w4.7: v3(14712.36,8873) 14712.52,8872.84 RN12.6@14712.52,8847.83 ; v4(17110.36,9187) 17110.93,9187.58 U2.35@17110.93,9236.63
  L6_SIG2 w5: v3(14712.36,8873) 14712.36,8974 14790.46,9052.1 15212.19,9052.1 15240.13,9024.16 15845.49,9024.16 cw(c15845.49,9018.21) 15851.45,9018.21 ccw(c15857.4,9018.21) 15857.4,9012.25 15870.49,9012.25 ccw(c15870.49,9018.21) 15876.45,9018.21 15876.45,9030.12 cw(c15882.4,9030.12) 15882.4,9036.07 15895.49,9036.07 cw(c15895.49,9030.12) 15901.45,9030.12 15901.45,9018.21 ccw(c15907.4,9018.21) 15907.4,9012.25 15920.49,9012.25 ccw(c15920.49,9018.21) 15926.45,9018.21 15926.45,9030.12 cw(c15932.4,9030.12) 15932.4,9036.07 15945.49,9036.07 cw(c15945.49,9030.12) 15951.45,9030.12 15951.45,9018.21 ccw(c15957.4,9018.21) 15957.4,9012.25 15970.49,9012.25 ccw(c15970.49,9018.21) 15976.45,9018.21 15976.45,9030.12 cw(c15982.4,9030.12) 15982.4,9036.07 15995.49,9036.07 cw(c15995.49,9030.12) 16001.45,9030.12 16001.45,9018.21 ccw(c16007.4,9018.21) 16007.4,9012.25 16020.49,9012.25 ccw(c16020.49,9018.21) 16026.45,9018.21 16026.45,9030.12 cw(c16032.4,9030.12) 16032.4,9036.07 16045.49,9036.07 cw(c16045.49,9030.12) 16051.45,9030.12 16051.45,9018.21 ccw(c16057.4,9018.21) 16057.4,9012.25 16070.49,9012.25 ccw(c16070.49,9018.21) 16076.45,9018.21 16076.45,9030.12 cw(c16082.4,9030.12) 16082.4,9036.07 16095.49,9036.07 cw(c16095.49,9030.12) 16101.45,9030.12 16101.45,9018.21 ccw(c16107.4,9018.21) 16107.4,9012.25 16120.49,9012.25 ccw(c16120.49,9018.21) 16126.45,9018.21 16126.45,9030.12 cw(c16132.4,9030.12) 16132.4,9036.07 16145.49,9036.07 cw(c16145.49,9030.12) 16151.45,9030.12 16151.45,9018.21 ccw(c16157.4,9018.21) 16157.4,9012.25 16170.49,9012.25 ccw(c16170.49,9018.21) 16176.45,9018.21 16176.45,9030.12 cw(c16182.4,9030.12) 16182.4,9036.07 16195.49,9036.07 cw(c16195.49,9030.12) 16201.45,9030.12 16201.45,9018.21 ccw(c16207.4,9018.21) 16207.4,9012.25 16220.49,9012.25 ccw(c16220.49,9018.21) 16226.45,9018.21 16226.45,9030.12 cw(c16232.4,9030.12) 16232.4,9036.07 16245.49,9036.07 cw(c16245.49,9030.12) 16251.45,9030.12 16251.45,9018.21 ccw(c16257.4,9018.21) 16257.4,9012.25 16270.49,9012.25 ccw(c16270.49,9018.21) 16276.45,9018.21 16276.45,9030.12 cw(c16282.4,9030.12) 16282.4,9036.07 16295.49,9036.07 cw(c16295.49,9030.12) 16301.45,9030.12 16301.45,9018.21 ccw(c16307.4,9018.21) 16307.4,9012.25 16320.49,9012.25 ccw(c16320.49,9018.21) 16326.45,9018.21 16326.45,9030.12 cw(c16332.4,9030.12) 16332.4,9036.07 16345.49,9036.07 cw(c16345.49,9030.12) 16351.45,9030.12 16351.45,9018.21 ccw(c16357.4,9018.21) 16357.4,9012.25 16370.49,9012.25 ccw(c16370.49,9018.21) 16376.45,9018.21 16376.45,9030.12 cw(c16382.4,9030.12) 16382.4,9036.07 16395.49,9036.07 cw(c16395.49,9030.12) 16401.45,9030.12 16401.45,9018.21 ccw(c16407.4,9018.21) 16407.4,9012.25 16420.49,9012.25 ccw(c16420.49,9018.21) 16426.45,9018.21 16426.45,9030.12 cw(c16432.4,9030.12) 16432.4,9036.07 16445.49,9036.07 cw(c16445.49,9030.12) 16451.45,9030.12 16451.45,9018.21 ccw(c16457.4,9018.21) 16457.4,9012.25 16470.49,9012.25 ccw(c16470.49,9018.21) 16476.45,9018.21 cw(c16482.4,9018.21) 16482.4,9024.16 17055.25,9024.16 17110.59,9079.5 17110.59,9186.77 v4(17110.36,9187)
TFP401_D21_FPGA: RN12.3 U8.A15 | length 514.6
  Top Layer w4.7: RN12.3@14712.52,8814.17 14712.79,8813.89 v3(14712.79,8771.54)
  Top Layer w10: U8.A15@14745.16,8329.4 v2(14764.84,8349.07)
  L6_SIG2 w5: v3(14712.79,8771.54) 14712.79,8532.94 14764.84,8480.9 v2(14764.84,8349.07)
TFP401_D22: RN12.7 U2.36 | length 3198
  Top Layer w4.7: RN12.7@14732.2,8847.83 v3(14732.2,8886) ; v4(17130.36,9186) 17130.94,9186.58 U2.36@17130.94,9233.9
  L6_SIG2 w5: v3(14732.2,8886) 14732.2,8961.84 14801.46,9031.1 15156.14,9031.1 15189.38,8997.87 15230.3,8997.87 cw(c15230.3,8991.39) 15236.78,8991.39 ccw(c15243.26,8991.39) 15243.26,8984.91 15255.3,8984.91 ccw(c15255.3,8991.39) 15261.78,8991.39 15261.78,9004.35 cw(c15268.26,9004.35) 15268.26,9010.83 15280.3,9010.83 cw(c15280.3,9004.35) 15286.78,9004.35 15286.78,8991.39 ccw(c15293.26,8991.39) 15293.26,8984.91 15305.3,8984.91 ccw(c15305.3,8991.39) 15311.78,8991.39 15311.78,9004.35 cw(c15318.26,9004.35) 15318.26,9010.83 15330.3,9010.83 cw(c15330.3,9004.35) 15336.78,9004.35 15336.78,8991.39 ccw(c15343.26,8991.39) 15343.26,8984.91 15355.3,8984.91 ccw(c15355.3,8991.39) 15361.78,8991.39 15361.78,9004.35 cw(c15368.26,9004.35) 15368.26,9010.83 15380.3,9010.83 cw(c15380.3,9004.35) 15386.78,9004.35 15386.78,8991.39 ccw(c15393.26,8991.39) 15393.26,8984.91 15405.3,8984.91 ccw(c15405.3,8991.39) 15411.78,8991.39 15411.78,9004.35 cw(c15418.26,9004.35) 15418.26,9010.83 15430.3,9010.83 cw(c15430.3,9004.35) 15436.78,9004.35 15436.78,8991.39 ccw(c15443.26,8991.39) 15443.26,8984.91 15455.3,8984.91 ccw(c15455.3,8991.39) 15461.78,8991.39 15461.78,9004.35 cw(c15468.26,9004.35) 15468.26,9010.83 15480.3,9010.83 cw(c15480.3,9004.35) 15486.78,9004.35 15486.78,8991.39 ccw(c15493.26,8991.39) 15493.26,8984.91 15505.3,8984.91 ccw(c15505.3,8991.39) 15511.78,8991.39 15511.78,9004.35 cw(c15518.26,9004.35) 15518.26,9010.83 15530.3,9010.83 cw(c15530.3,9004.35) 15536.78,9004.35 15536.78,8991.39 ccw(c15543.26,8991.39) 15543.26,8984.91 15555.3,8984.91 ccw(c15555.3,8991.39) 15561.78,8991.39 15561.78,9004.35 cw(c15568.26,9004.35) 15568.26,9010.83 15580.3,9010.83 cw(c15580.3,9004.35) 15586.78,9004.35 15586.78,8991.39 ccw(c15593.26,8991.39) 15593.26,8984.91 15605.3,8984.91 ccw(c15605.3,8991.39) 15611.78,8991.39 15611.78,9004.35 cw(c15618.26,9004.35) 15618.26,9010.83 15630.3,9010.83 cw(c15630.3,9004.35) 15636.78,9004.35 15636.78,8991.39 ccw(c15643.26,8991.39) 15643.26,8984.91 15655.3,8984.91 ccw(c15655.3,8991.39) 15661.78,8991.39 15661.78,9004.35 cw(c15668.26,9004.35) 15668.26,9010.83 15680.3,9010.83 cw(c15680.3,9004.35) 15686.78,9004.35 15686.78,8991.39 ccw(c15693.26,8991.39) 15693.26,8984.91 15705.3,8984.91 ccw(c15705.3,8991.39) 15711.78,8991.39 15711.78,9004.35 cw(c15718.26,9004.35) 15718.26,9010.83 15730.3,9010.83 cw(c15730.3,9004.35) 15736.78,9004.35 15736.78,8991.39 ccw(c15743.26,8991.39) 15743.26,8984.91 15755.3,8984.91 ccw(c15755.3,8991.39) 15761.78,8991.39 15761.78,9004.35 cw(c15768.26,9004.35) 15768.26,9010.83 15780.3,9010.83 cw(c15780.3,9004.35) 15786.78,9004.35 ccw(c15793.26,9004.35) 15793.26,8997.87 17068.18,8997.87 17130.67,9060.35 17130.67,9185.69 v4(17130.36,9186) v4@17130.36,9187
TFP401_D22_FPGA: RN12.2 U8.E16 | length 680.2
  Top Layer w4.7: RN12.2@14732.2,8814.17 14733.36,8813.01 v3(14733.36,8785.7)
  Top Layer w10: U8.E16@14784.52,8171.9 v2(14804.2,8191.57)
  L6_SIG2 w5: v3(14733.36,8785.7) 14733.36,8537.61 14779.34,8491.63 14779.34,8216.43 v2(14804.2,8191.57)
TFP401_D23: RN12.8 U2.37 | length 3238.7
  Top Layer w4.7: RN12.8@14751.89,8847.83 v3(14751.89,8873) ; U2.37@17150.04,9232.39 17150.36,9232.07 v4(17150.36,9187)
  L6_SIG2 w5: v3(14751.89,8873) 14751.89,8947.53 14815.46,9011.1 15120.1,9011.1 15160.97,8970.24 16203.54,8970.24 ccw(c16203.54,8975.59) 16208.89,8975.59 cw(c16214.24,8975.59) 16214.24,8980.94 16228.54,8980.94 cw(c16228.54,8975.59) 16233.89,8975.59 16233.89,8964.88 ccw(c16239.24,8964.88) 16239.24,8959.53 16253.54,8959.53 ccw(c16253.54,8964.88) 16258.89,8964.88 16258.89,8975.59 cw(c16264.24,8975.59) 16264.24,8980.94 16278.54,8980.94 cw(c16278.54,8975.59) 16283.89,8975.59 16283.89,8964.88 ccw(c16289.24,8964.88) 16289.24,8959.53 16303.54,8959.53 ccw(c16303.54,8964.88) 16308.89,8964.88 16308.89,8975.59 cw(c16314.24,8975.59) 16314.24,8980.94 16328.54,8980.94 cw(c16328.54,8975.59) 16333.89,8975.59 16333.89,8964.88 ccw(c16339.24,8964.88) 16339.24,8959.53 16353.54,8959.53 ccw(c16353.54,8964.88) 16358.89,8964.88 16358.89,8975.59 cw(c16364.24,8975.59) 16364.24,8980.94 16378.54,8980.94 cw(c16378.54,8975.59) 16383.89,8975.59 16383.89,8964.88 ccw(c16389.24,8964.88) 16389.24,8959.53 16403.54,8959.53 ccw(c16403.54,8964.88) 16408.89,8964.88 16408.89,8975.59 cw(c16414.24,8975.59) 16414.24,8980.94 16428.54,8980.94 cw(c16428.54,8975.59) 16433.89,8975.59 16433.89,8964.88 ccw(c16439.24,8964.88) 16439.24,8959.53 16453.54,8959.53 ccw(c16453.54,8964.88) 16458.89,8964.88 16458.89,8975.59 cw(c16464.24,8975.59) 16464.24,8980.94 16478.54,8980.94 cw(c16478.54,8975.59) 16483.89,8975.59 16483.89,8964.88 ccw(c16489.24,8964.88) 16489.24,8959.53 16503.54,8959.53 ccw(c16503.54,8964.88) 16508.89,8964.88 16508.89,8975.59 cw(c16514.24,8975.59) 16514.24,8980.94 16528.54,8980.94 cw(c16528.54,8975.59) 16533.89,8975.59 16533.89,8964.88 ccw(c16539.24,8964.88) 16539.24,8959.53 16553.54,8959.53 ccw(c16553.54,8964.88) 16558.89,8964.88 16558.89,8975.59 cw(c16564.24,8975.59) 16564.24,8980.94 16578.54,8980.94 cw(c16578.54,8975.59) 16583.89,8975.59 16583.89,8964.88 ccw(c16589.24,8964.88) 16589.24,8959.53 16603.54,8959.53 ccw(c16603.54,8964.88) 16608.89,8964.88 16608.89,8975.59 cw(c16614.24,8975.59) 16614.24,8980.94 16628.54,8980.94 cw(c16628.54,8975.59) 16633.89,8975.59 16633.89,8964.88 ccw(c16639.24,8964.88) 16639.24,8959.53 16653.54,8959.53 ccw(c16653.54,8964.88) 16658.89,8964.88 16658.89,8975.59 cw(c16664.24,8975.59) 16664.24,8980.94 16678.54,8980.94 cw(c16678.54,8975.59) 16683.89,8975.59 16683.89,8964.88 ccw(c16689.24,8964.88) 16689.24,8959.53 16703.54,8959.53 ccw(c16703.54,8964.88) 16708.89,8964.88 16708.89,8975.59 cw(c16714.24,8975.59) 16714.24,8980.94 16728.54,8980.94 cw(c16728.54,8975.59) 16733.89,8975.59 16733.89,8964.88 ccw(c16739.24,8964.88) 16739.24,8959.53 16753.54,8959.53 ccw(c16753.54,8964.88) 16758.89,8964.88 16758.89,8975.59 cw(c16764.24,8975.59) 16764.24,8980.94 16778.54,8980.94 cw(c16778.54,8975.59) 16783.89,8975.59 16783.89,8964.88 ccw(c16789.24,8964.88) 16789.24,8959.53 16803.54,8959.53 ccw(c16803.54,8964.88) 16808.89,8964.88 16808.89,8975.59 cw(c16814.24,8975.59) 16814.24,8980.94 16828.54,8980.94 cw(c16828.54,8975.59) 16833.89,8975.59 16833.89,8964.88 ccw(c16839.24,8964.88) 16839.24,8959.53 16853.54,8959.53 ccw(c16853.54,8964.88) 16858.89,8964.88 16858.89,8975.59 cw(c16864.24,8975.59) 16864.24,8980.94 16878.54,8980.94 cw(c16878.54,8975.59) 16883.89,8975.59 16883.89,8964.88 ccw(c16889.24,8964.88) 16889.24,8959.53 16903.54,8959.53 ccw(c16903.54,8964.88) 16908.89,8964.88 cw(c16914.24,8964.88) 16914.24,8970.24 17096.49,8970.24 17150.57,9024.32 17150.57,9186.78 v4(17150.36,9187)
TFP401_D23_FPGA: RN12.1 U8.C16 | length 593.3
  Top Layer w4.7: RN12.1@14751.89,8814.17 14753.81,8812.24 v3(14753.81,8771.5)
  Top Layer w10: U8.C16@14784.52,8250.65 v2(14804.2,8270.32)
  L6_SIG2 w5: v3@14753.87,8771.44 14753.87,8550.55 14791.14,8513.29 14791.14,8283.38 v2(14804.2,8270.32)
TFP401_DE: RN21.5 U2.46 | length 3185.2
  Top Layer w4.7: RN21.5@14887.83,8847.83 v3(14887.83,8887) ; U2.46@17326.64,9234.27 17326.64,9187.72 v4(17327.36,9187)
  L6_SIG2 w5: v3(14887.83,8887) 14887.83,8910.47 14898.73,8921.37 14979.61,8921.37 15027.34,8873.64 16506.28,8873.64 ccw(c16506.28,8878.38) 16511.02,8878.38 cw(c16515.76,8878.38) 16515.76,8883.12 16531.28,8883.12 cw(c16531.28,8878.38) 16536.02,8878.38 16536.02,8868.9 ccw(c16540.76,8868.9) 16540.76,8864.16 16556.28,8864.16 ccw(c16556.28,8868.9) 16561.02,8868.9 16561.02,8878.38 cw(c16565.76,8878.38) 16565.76,8883.12 16581.28,8883.12 cw(c16581.28,8878.38) 16586.02,8878.38 16586.02,8868.9 ccw(c16590.76,8868.9) 16590.76,8864.16 16606.28,8864.16 ccw(c16606.28,8868.9) 16611.02,8868.9 16611.02,8878.38 cw(c16615.76,8878.38) 16615.76,8883.12 16631.28,8883.12 cw(c16631.28,8878.38) 16636.02,8878.38 16636.02,8868.9 ccw(c16640.76,8868.9) 16640.76,8864.16 16656.28,8864.16 ccw(c16656.28,8868.9) 16661.02,8868.9 16661.02,8878.38 cw(c16665.76,8878.38) 16665.76,8883.12 16681.28,8883.12 cw(c16681.28,8878.38) 16686.02,8878.38 16686.02,8868.9 ccw(c16690.76,8868.9) 16690.76,8864.16 16706.28,8864.16 ccw(c16706.28,8868.9) 16711.02,8868.9 16711.02,8878.38 cw(c16715.76,8878.38) 16715.76,8883.12 16731.28,8883.12 cw(c16731.28,8878.38) 16736.02,8878.38 16736.02,8868.9 ccw(c16740.76,8868.9) 16740.76,8864.16 16756.28,8864.16 ccw(c16756.28,8868.9) 16761.02,8868.9 16761.02,8878.38 cw(c16765.76,8878.38) 16765.76,8883.12 16781.28,8883.12 cw(c16781.28,8878.38) 16786.02,8878.38 16786.02,8868.9 ccw(c16790.76,8868.9) 16790.76,8864.16 16806.28,8864.16 ccw(c16806.28,8868.9) 16811.02,8868.9 16811.02,8878.38 cw(c16815.76,8878.38) 16815.76,8883.12 16831.28,8883.12 cw(c16831.28,8878.38) 16836.02,8878.38 16836.02,8868.9 ccw(c16840.76,8868.9) 16840.76,8864.16 16856.28,8864.16 ccw(c16856.28,8868.9) 16861.02,8868.9 16861.02,8878.38 cw(c16865.76,8878.38) 16865.76,8883.12 16881.28,8883.12 cw(c16881.28,8878.38) 16886.02,8878.38 16886.02,8868.9 ccw(c16890.76,8868.9) 16890.76,8864.16 16906.28,8864.16 ccw(c16906.28,8868.9) 16911.02,8868.9 16911.02,8878.38 cw(c16915.76,8878.38) 16915.76,8883.12 16931.28,8883.12 cw(c16931.28,8878.38) 16936.02,8878.38 16936.02,8868.9 ccw(c16940.76,8868.9) 16940.76,8864.16 16956.28,8864.16 ccw(c16956.28,8868.9) 16961.02,8868.9 16961.02,8878.38 cw(c16965.76,8878.38) 16965.76,8883.12 16981.28,8883.12 cw(c16981.28,8878.38) 16986.02,8878.38 16986.02,8868.9 ccw(c16990.76,8868.9) 16990.76,8864.16 17006.28,8864.16 ccw(c17006.28,8868.9) 17011.02,8868.9 17011.02,8878.38 cw(c17015.76,8878.38) 17015.76,8883.12 17031.28,8883.12 cw(c17031.28,8878.38) 17036.02,8878.38 17036.02,8868.9 ccw(c17040.76,8868.9) 17040.76,8864.16 17056.28,8864.16 ccw(c17056.28,8868.9) 17061.02,8868.9 17061.02,8878.38 cw(c17065.76,8878.38) 17065.76,8883.12 17081.28,8883.12 cw(c17081.28,8878.38) 17086.02,8878.38 17086.02,8868.9 ccw(c17090.76,8868.9) 17090.76,8864.16 17106.28,8864.16 ccw(c17106.28,8868.9) 17111.02,8868.9 cw(c17115.76,8868.9) 17115.76,8873.64 17232.52,8873.64 17280.25,8921.37 17280.45,8921.37 17327.36,8968.28 v4(17327.36,9187)
TFP401_DE_FPGA: RN21.4 U8.C17 | length 590.9
  Top Layer w4.7: RN21.4@14887.83,8814.17 14888.96,8813.04 v3(14888.96,8786.44)
  Top Layer w10: U8.C17@14823.89,8250.65 v2(14843.57,8270.32)
  L6_SIG2 w5: v2(14843.57,8270.32) 14856.95,8283.71 14856.95,8738.56 14888.96,8770.56 v3(14888.96,8786.44)
TFP401_HSYNC: RN21.7 U2.48 | length 3383.1
  Top Layer w4.7: RN21.7@14927.2,8847.83 14927.2,8886.84 v3(14927.36,8887) ; v4(17366.36,9186) 17366.8,9186.45 U2.48@17366.8,9242.91
  L6_SIG2 w5: v3(14927.36,8887) 14927.36,8838.22 14941.37,8824.2 15970.52,8824.2 cw(c15970.52,8811.7) 15983.02,8811.7 15983.02,8792.67 ccw(c15995.52,8792.67) 16008.02,8792.67 16008.02,8811.7 cw(c16020.52,8811.7) 16033.02,8811.7 16033.02,8792.67 ccw(c16045.52,8792.67) 16058.02,8792.67 16058.02,8811.7 cw(c16070.52,8811.7) 16083.02,8811.7 16083.02,8792.67 ccw(c16095.52,8792.67) 16108.02,8792.67 16108.02,8811.7 cw(c16120.52,8811.7) 16133.02,8811.7 16133.02,8792.67 ccw(c16145.52,8792.67) 16158.02,8792.67 16158.02,8811.7 cw(c16170.52,8811.7) 16183.02,8811.7 16183.02,8792.67 ccw(c16195.52,8792.67) 16208.02,8792.67 16208.02,8811.7 cw(c16220.52,8811.7) 16233.02,8811.7 16233.02,8792.67 ccw(c16245.52,8792.67) 16258.02,8792.67 16258.02,8811.7 cw(c16270.52,8811.7) 16283.02,8811.7 16283.02,8792.67 ccw(c16295.52,8792.67) 16308.02,8792.67 16308.02,8811.7 cw(c16320.52,8811.7) 16320.52,8824.2 17306.72,8824.2 17366.36,8883.84 v4(17366.36,9186)
TFP401_HSYNC_FPGA: RN21.2 U8.A18 | length 511.4
  Top Layer w4.7: v3(14926.06,8788.75) 14927.2,8789.89 RN21.2@14927.2,8814.17
  Top Layer w7.9: U8.A18@14863.26,8329.4 v2(14882.94,8349.07)
  L6_SIG2 w5: v2(14882.94,8349.07) 14882.94,8690.13 14926.17,8733.37 14926.17,8788.64 v3(14926.06,8788.75)
TFP401_ODCK: R190.1 U2.44 | length 3875.3
  Top Layer w4.7: U2.44@17287.69,9244.43 17287.69,9186.67 v4(17289.36,9185)
  Bottom Layer w4.7: R190.1@14508.36,8366.04 14508.36,8671 14586.36,8749 16982.51,8749 17010.51,8721 ccw(c17010.51,8731) 17020.51,8731 17020.51,8749 cw(c17030.51,8749) 17040.51,8749 17040.51,8731 ccw(c17050.51,8731) 17060.51,8731 17060.51,8749 cw(c17070.51,8749) 17080.51,8749 17080.51,8731 ccw(c17090.51,8731) 17100.51,8731 17100.51,8749 cw(c17110.51,8749) 17120.51,8749 17120.51,8731 ccw(c17130.51,8731) 17140.51,8731 17140.51,8749 cw(c17150.51,8749) 17160.51,8749 17160.51,8731 ccw(c17170.51,8731) 17170.51,8721 17265.36,8721 17289.36,8745 v4(17289.36,9185)
TFP401_ODCK_FPGA: R190.2 U8.B10 | length 58.5
  Top Layer w10: v2(14528.63,8309.69) U8.B10@14548.3,8290.01
  Bottom Layer w4.7: R190.2@14508.36,8331.96 14508.36,8329.96 v2(14528.63,8309.69)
